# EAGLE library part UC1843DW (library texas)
PULSE WIDTH MODULATOR
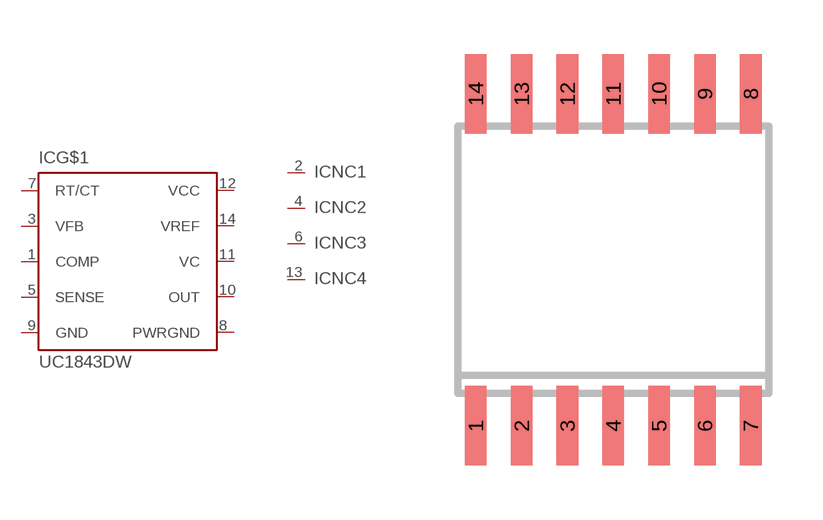
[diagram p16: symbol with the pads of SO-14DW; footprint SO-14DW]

Designator prefix IC; gates G$1=UC1843 NC1=NC NC2=NC NC3=NC NC4=NC

## UC1843DW (OC_FARNELL: unknown; OC_NEWARK: unknown)  [SO-14DW]
1  G$1:COMP  pas
2  NC1:NC  nc
3  G$1:VFB  in
4  NC2:NC  nc
5  G$1:SENSE  in
6  NC3:NC  nc
7  G$1:RT/CT  pas
8  G$1:PWRGND  pwr
9  G$1:GND  pwr
10  G$1:OUT  out
11  G$1:VC  in
12  G$1:VCC  pwr
13  NC4:NC  nc
14  G$1:VREF  out

## Footprint SO-14DW (pad centres in mm)
Small Outline Integrated Circuit wide
smd 0.6 x 2.2: 1 -3.81,-4.6; 2 -2.54,-4.6; 3 -1.27,-4.6; 4 0,-4.6; 5 1.27,-4.6; 6 2.54,-4.6; 7 3.81,-4.6; 8 3.81,4.6; 9 2.54,4.6; 10 1.27,4.6; 11 0,4.6; 12 -1.27,4.6; 13 -2.54,4.6; 14 -3.81,4.6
